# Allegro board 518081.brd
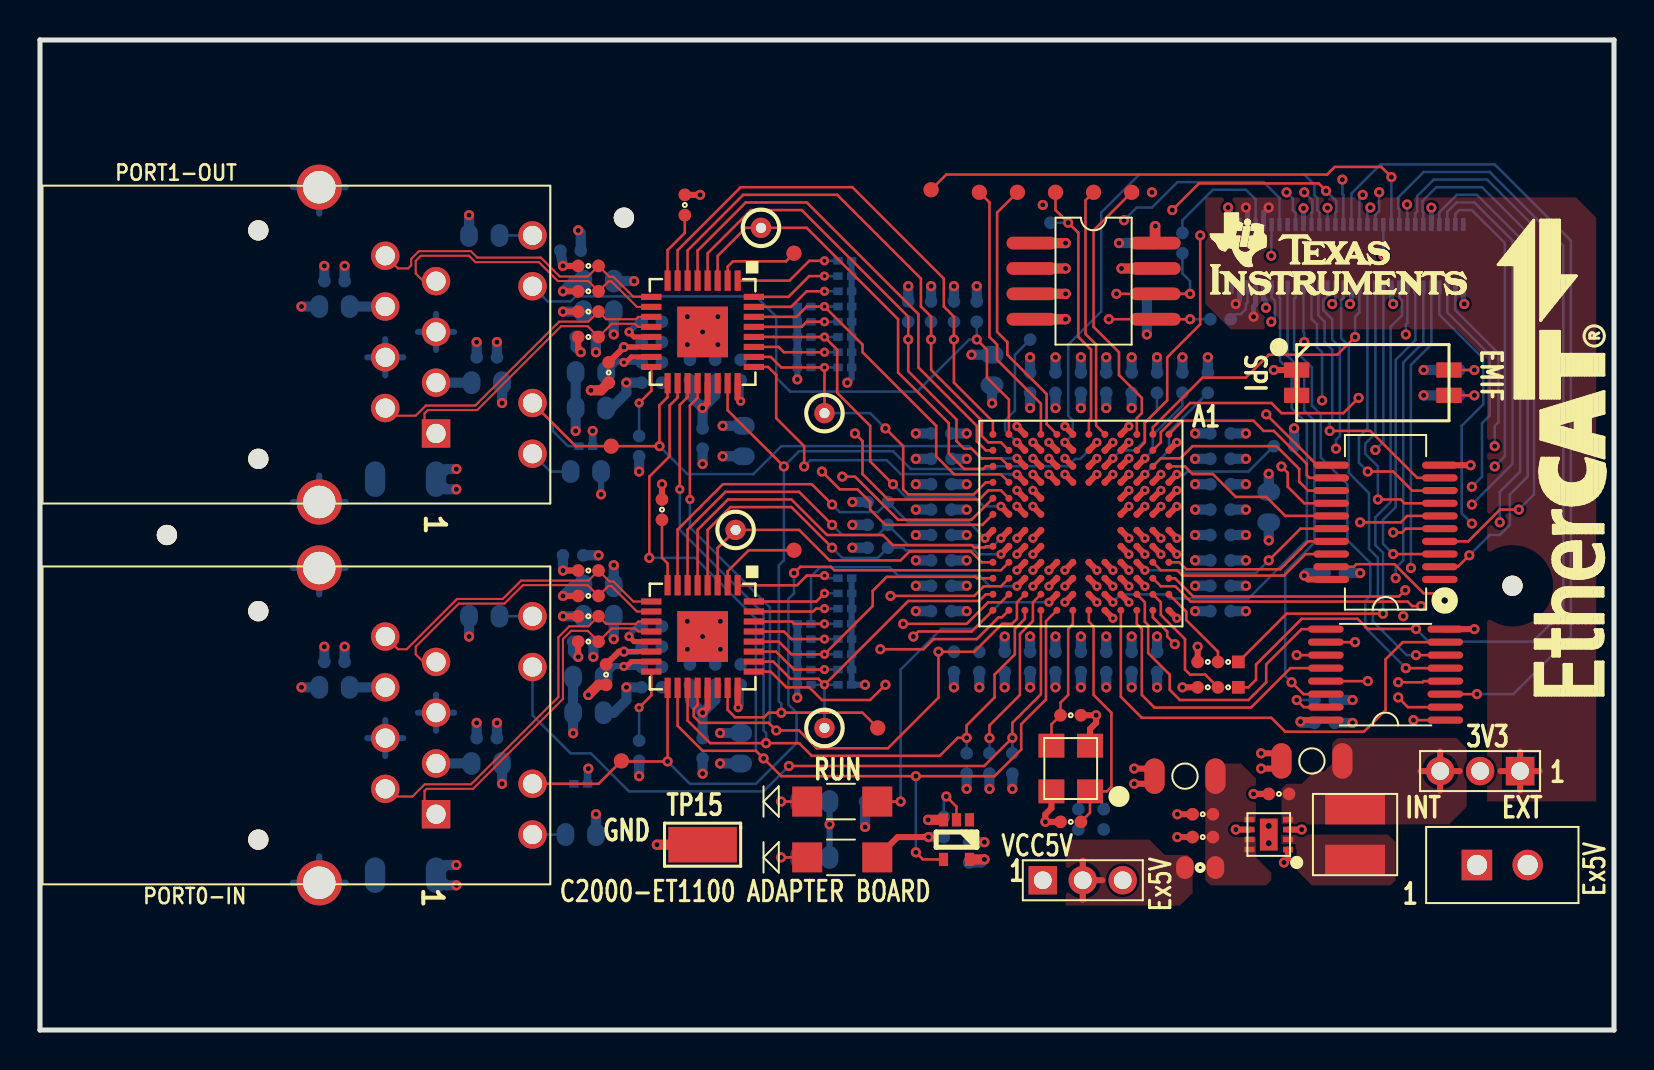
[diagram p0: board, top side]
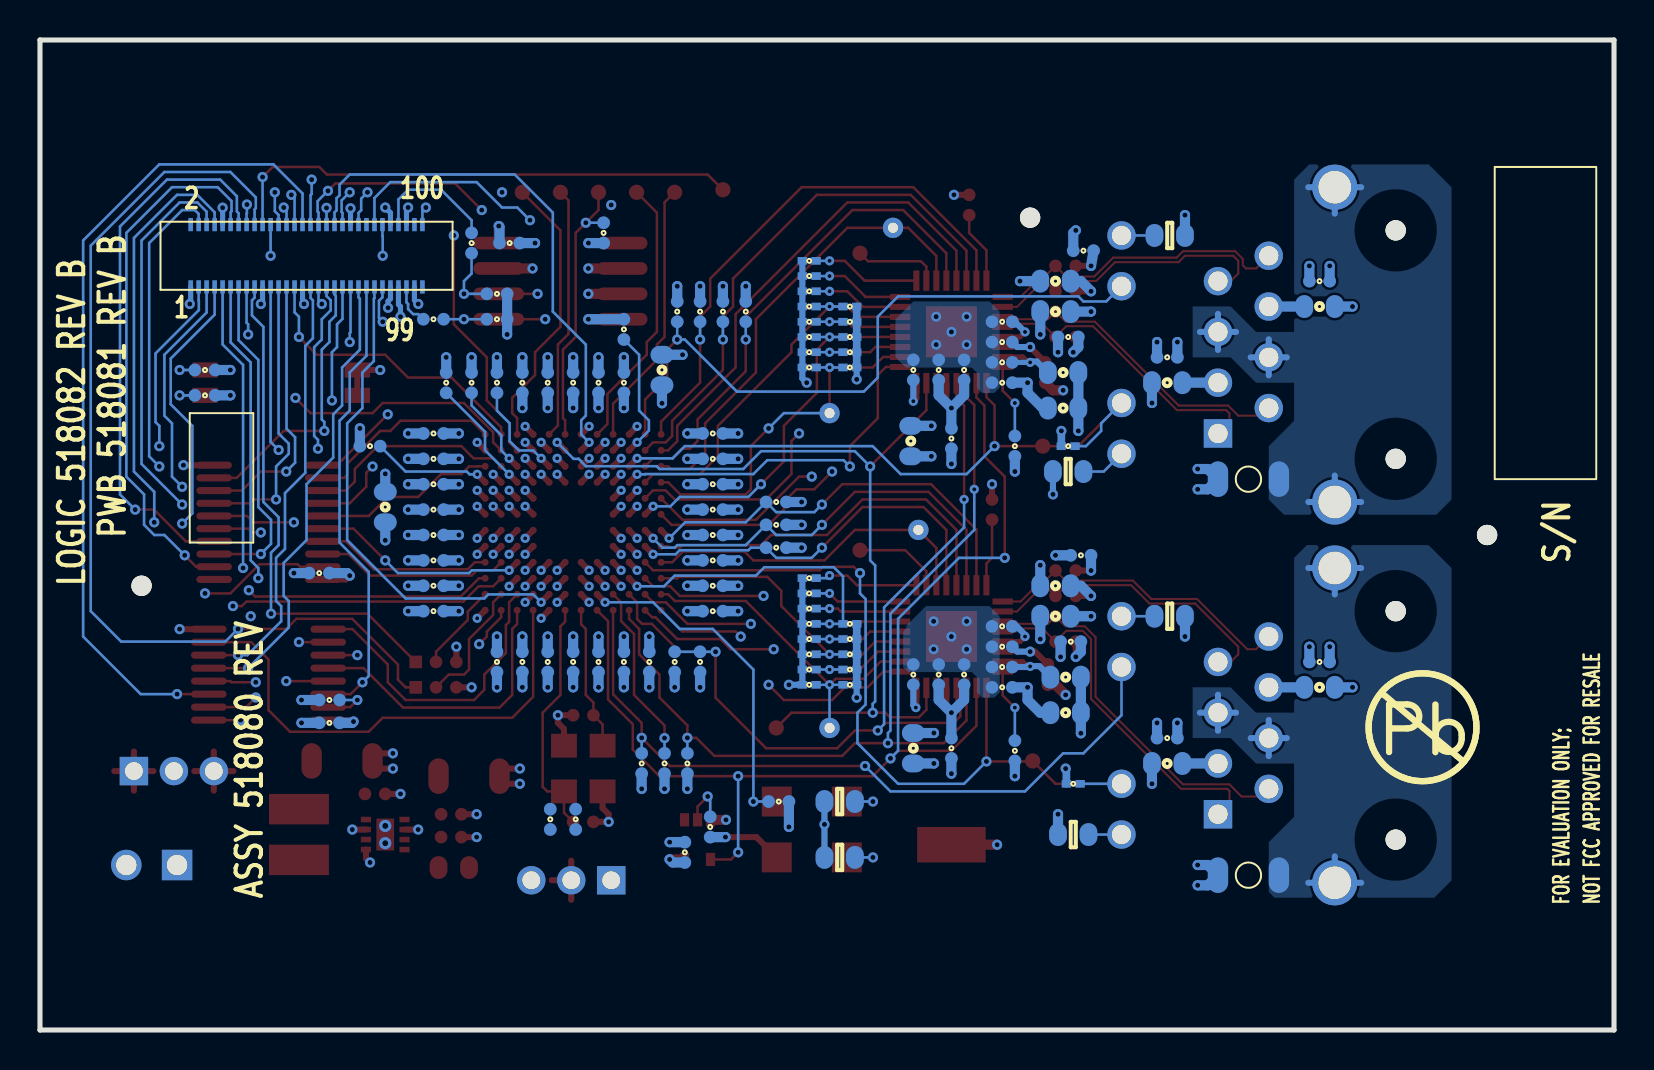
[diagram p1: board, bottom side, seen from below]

Outline 78.74 x 49.53 mm; copper layers: TOP, L2_GND, L3_ROUTE, L4_ROUTE, L5_PWR, BOTTOM. Coordinates in mm from the lower left corner of the outline.
Outline path: 0,49.53 78.74,49.53 78.74,0 0,0 0,49.53

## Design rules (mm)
net group MII0_RX1: nets MII0_RXM1 MII0_RXP1
net group MII0_TX1: nets MII0_TXM1 MII0_TXP1
net group MII1_RX1: nets MII1_RXM1 MII1_RXP1
net group MII1_TX1: nets MII1_TXM1 MII1_TXP1

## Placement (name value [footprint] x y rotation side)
C1  100pF  [C402-25]  28.45 32.89 270 top
C2  100pF  [C402-25]  28.32 17.78 270 top
C3  COMPONENTVALUE  [C402-25]  51.56 15.75 0 top
C4  X  [C1206-40X70]  63.63 13.46 180 top
C5  COMPONENTVALUE  [C402-25]  61.98 11.81 180 top
C6  X  [C1206-40X70]  57.28 12.7 180 top
C7  COMPONENTVALUE  [C402-25]  51.56 10.41 180 top
C8  COMPONENTVALUE  [C402-25]  58.17 10.79 180 top
C9  COMPONENTVALUE  [C402-25]  58.17 9.65 180 top
C10  COMPONENTVALUE  [C402-25]  46.48 8.89 90 bottom
C11  0.1uF  [C402-25]  26.54 38.99 180 bottom
C12  1uF  [C603-35X45]  27.94 37.47 0 bottom
C13  0.1uF  [C402-25]  14.73 37.47 180 bottom
C14  1uF  [C603-35X45]  14.73 36.2 180 bottom
C15  1uF  [C603-35X45]  27.94 35.94 180 bottom
C16  0.1uF  [C402-25]  30.61 35.43 0 bottom
C17  0.1uF  [C402-25]  27.3 34.67 0 bottom
C18  10nF  [C402-25]  30.61 34.42 0 bottom
C19  COMPONENTVALUE  [C402-25]  64.77 22.86 0 bottom
C20  0.1uF  [C402-25]  22.35 33.66 0 bottom
C21  0.1uF  [C402-25]  30.61 33.4 0 bottom
C22  X  [C603-35X45]  47.62 33.02 90 bottom
C23  0.1uF  [C402-25]  35.05 33.02 90 bottom
C24  10nF  [C402-25]  33.78 33.02 90 bottom
C25  1nF  [C402-25]  32.51 33.02 90 bottom
C26  10uF  [C603-35X45]  27.56 32.89 180 bottom
C27  COMPONENTVALUE  [C402-25]  54.61 32.38 90 bottom
C28  COMPONENTVALUE  [C402-25]  53.34 32.38 90 bottom
C29  COMPONENTVALUE  [C402-25]  52.07 32.38 90 bottom
C30  COMPONENTVALUE  [C402-25]  50.8 32.38 90 bottom
C31  COMPONENTVALUE  [C402-25]  49.53 32.38 90 bottom
C32  1nF  [C402-25]  30.61 32.38 0 bottom
C33  1uF  [C603-35X45]  22.35 32.38 0 bottom
C34  10uF  [C603-35X45]  27.56 31.11 180 bottom
C35  COMPONENTVALUE  [C402-25]  59.05 29.84 0 bottom
C36  COMPONENTVALUE  [C402-25]  45.09 29.84 180 bottom
C37  100pF  [C402-25]  33.15 29.59 270 bottom
C38  10uF  [C603-35X45]  35.18 29.46 270 bottom
C39  COMPONENTVALUE  [C402-25]  59.05 28.57 0 bottom
C40  COMPONENTVALUE  [C402-25]  45.09 28.57 180 bottom
C41  4700pF  [C1206-40X70]  18.29 27.56 180 bottom
C42  COMPONENTVALUE  [C402-25]  59.05 27.3 0 bottom
C43  COMPONENTVALUE  [C402-25]  45.09 27.3 180 bottom
C44  X  [C603-35X45]  61.47 26.16 90 bottom
C45  COMPONENTVALUE  [C402-25]  59.05 26.04 0 bottom
C46  COMPONENTVALUE  [C402-25]  45.09 26.04 180 bottom
C47  COMPONENTVALUE  [C402-25]  55.24 39.37 0 bottom
C48  COMPONENTVALUE  [C402-25]  59.05 24.77 0 bottom
C49  COMPONENTVALUE  [C402-25]  45.09 24.77 180 bottom
C50  0.1uF  [C402-25]  26.67 23.75 0 bottom
C51  COMPONENTVALUE  [C402-25]  59.05 23.5 0 bottom
C52  COMPONENTVALUE  [C402-25]  45.09 23.5 180 bottom
C53  COMPONENTVALUE  [C402-25]  59.05 22.23 0 bottom
C54  COMPONENTVALUE  [C402-25]  45.09 22.23 180 bottom
C55  1uF  [C603-35X45]  27.94 22.23 0 bottom
C56  COMPONENTVALUE  [C402-25]  59.05 20.95 0 bottom
C57  COMPONENTVALUE  [C402-25]  45.09 20.95 180 bottom
C58  1uF  [C603-35X45]  27.94 20.7 180 bottom
C59  0.1uF  [C402-25]  30.61 20.19 0 bottom
C60  0.1uF  [C402-25]  27.18 19.43 180 bottom
C61  10nF  [C402-25]  30.61 19.18 0 bottom
C62  COMPONENTVALUE  [C402-25]  55.88 18.41 270 bottom
C63  COMPONENTVALUE  [C402-25]  54.61 18.41 270 bottom
C64  COMPONENTVALUE  [C402-25]  53.34 18.41 270 bottom
C65  COMPONENTVALUE  [C402-25]  52.07 18.41 270 bottom
C66  COMPONENTVALUE  [C402-25]  50.8 18.41 270 bottom
C67  COMPONENTVALUE  [C402-25]  49.53 18.41 270 bottom
C68  COMPONENTVALUE  [C402-25]  48.26 18.41 270 bottom
C69  0.1uF  [C402-25]  14.73 18.41 180 bottom
C70  0.1uF  [C402-25]  30.61 18.16 0 bottom
C71  0.1uF  [C402-25]  35.05 17.78 90 bottom
C72  10nF  [C402-25]  33.78 17.78 90 bottom
C73  1nF  [C402-25]  32.51 17.78 90 bottom
C74  10uF  [C603-35X45]  27.43 17.65 180 bottom
C75  COMPONENTVALUE  [C402-25]  64.26 15.37 0 bottom
C76  1nF  [C402-25]  30.61 17.14 0 bottom
C77  1uF  [C603-35X45]  14.73 17.14 180 bottom
C78  10uF  [C603-35X45]  27.43 15.88 180 bottom
C79  0.1uF  [C402-25]  22.35 14.61 0 bottom
C80  10uF  [C603-35X45]  35.05 14.1 270 bottom
C81  100pF  [C402-25]  33.15 14.1 270 bottom
C82  1uF  [C603-35X45]  22.35 13.34 0 bottom
C83  4700pF  [C1206-40X70]  18.29 7.75 180 bottom
DS1  X  [LED1206-59X59]  40.13 11.43 0 top
DS2  X  [LED1206-59X59]  40.13 8.64 0 top
J3  X  [HDR1X3-6040-2MM]  74.04 12.95 180 top
J6  VALUE  [DF40C_60DS]  65.41 38.73 180 bottom
J9  X  [CONN2-EH]  71.88 8.26 0 top
J10  X  [HDR1X3-6040-2MM]  50.16 7.49 0 top
L1  0  [L603-35X45]  58.04 8.13 0 top
L2  X  [IND-LQH44P]  65.79 9.78 90 top
NOREF  -  [unnamed]  73.66 22.23 0 top
NOREF#2  -  [#2]  -259.21 -252.98 0 top
NOREF#3  -  [#2]  -259.21 -252.98 0 top
NOREF#4  -  [unnamed]  29.21 40.64 0 top
NOREF#5  -  [#2]  85.98 16.76 0 top
NOREF#6  -  [unnamed]  6.35 24.77 0 top
NOREF#7  -  [#2]  12.95 11.68 180 bottom
P0  -  [RJ45-PULSE_J1-SHLD]  19.81 10.79 270 top
P1  -  [RJ45-PULSE_J1-SHLD]  19.81 29.84 270 top
R1  10K  [R402-25]  32.26 41.27 270 top
R2  49.9  [R402-25]  27.43 38.23 180 top
R3  49.9  [R402-25]  27.43 36.96 180 top
R4  49.9  [R402-25]  27.43 35.94 180 top
R5  49.9  [R402-25]  27.43 34.67 180 top
R6  COMPONENTVALUE  [R402-25]  59.05 35.56 0 bottom
R7  COMPONENTVALUE  [R402-25]  57.15 39.37 270 bottom
R8  10K  [R402-25]  31.11 26.04 270 top
R9  49.9  [R402-25]  27.43 22.99 180 top
R10  49.9  [R402-25]  27.43 21.72 180 top
R11  49.9  [R402-25]  27.43 20.7 180 top
R12  49.9  [R402-25]  27.43 19.43 180 top
R13  COMPONENTVALUE  [R402-25]  45.21 10.16 270 bottom
R14  X  [R603-35X45]  22.23 39.75 180 bottom
R15  2.2K  [R201-18P5X15]  40.26 38.48 0 bottom
R16  2.2K  [R201-18P5X15]  40.26 37.72 0 bottom
R17  2.2K  [R201-18P5X15]  40.26 36.96 0 bottom
R18  COMPONENTVALUE  [R402-25]  57.15 32.38 90 bottom
R19  COMPONENTVALUE  [R402-25]  58.42 32.38 90 bottom
R20  COMPONENTVALUE  [R402-25]  55.88 32.38 90 bottom
R21  COMPONENTVALUE  [R402-25]  50.55 39.88 90 bottom
R22  2.2K  [R201-18P5X15]  40.26 36.2 0 bottom
R23  NO-POP  [R201-18P5X15]  38.23 36.2 0 bottom
R24  COMPONENTVALUE  [R402-25]  49.53 35.05 90 bottom
R25  COMPONENTVALUE  [R402-25]  46.86 35.94 90 bottom
R26  COMPONENTVALUE  [R402-25]  45.72 35.94 90 bottom
R27  COMPONENTVALUE  [R402-25]  44.58 35.94 90 bottom
R28  COMPONENTVALUE  [R402-25]  43.43 35.94 90 bottom
R29  NO-POP  [R201-18P5X15]  40.26 35.43 0 bottom
R30  2.2K  [R201-18P5X15]  38.23 35.43 0 bottom
R31  NO-POP  [R201-18P5X15]  40.26 34.67 0 bottom
R32  2.2K  [R201-18P5X15]  38.23 34.67 0 bottom
R33  COMPONENTVALUE  [R402-25]  70.48 33.02 180 bottom
R34  COMPONENTVALUE  [R402-25]  70.48 31.75 180 bottom
R35  NO-POP  [R201-18P5X15]  40.26 33.91 0 bottom
R36  2.2K  [R201-18P5X15]  38.23 33.91 0 bottom
R37  2.2K  [R201-18P5X15]  40.26 33.15 0 bottom
R38  NO-POP  [R201-18P5X15]  38.23 33.15 0 bottom
R39  COMPONENTVALUE  [R402-25]  62.23 29.21 180 bottom
R40  4.87K 1%  [R402-25]  29.97 29.21 270 bottom
R41  2.2K  [R201-18P5X15]  27.3 29.21 180 bottom
R42  COMPONENTVALUE  [R402-25]  55.88 35.56 180 bottom
R43  330  [R603-35X45]  27.3 27.94 0 bottom
R44  COMPONENTVALUE  [R402-25]  55.88 36.83 180 bottom
R45  COMPONENTVALUE  [R402-25]  41.91 26.42 180 bottom
R46  COMPONENTVALUE  [R402-25]  41.91 25.27 180 bottom
R47  COMPONENTVALUE  [R402-25]  41.91 24.13 180 bottom
R48  2.2K  [R201-18P5X15]  40.26 22.61 0 bottom
R49  2.2K  [R201-18P5X15]  40.26 21.84 0 bottom
R50  2.2K  [R201-18P5X15]  40.26 21.08 0 bottom
R51  X  [R603-35X45]  22.23 20.7 180 bottom
R52  2.2K  [R201-18P5X15]  40.26 20.32 0 bottom
R53  NO-POP  [R201-18P5X15]  38.23 20.32 0 bottom
R54  2.2K  [R201-18P5X15]  40.26 19.56 0 bottom
R55  NO-POP  [R201-18P5X15]  38.23 19.56 0 bottom
R56  NO-POP  [R201-18P5X15]  40.26 18.8 0 bottom
R57  2.2K  [R201-18P5X15]  38.23 18.8 0 bottom
R58  COMPONENTVALUE  [R402-25]  64.26 16.51 180 bottom
R59  COMPONENTVALUE  [R402-25]  46.99 18.41 270 bottom
R60  COMPONENTVALUE  [R402-25]  45.72 18.41 270 bottom
R61  NO-POP  [R201-18P5X15]  40.26 18.03 0 bottom
R62  2.2K  [R201-18P5X15]  38.23 18.03 0 bottom
R63  2.2K  [R201-18P5X15]  40.26 17.27 0 bottom
R64  NO-POP  [R201-18P5X15]  38.23 17.27 0 bottom
R65  4.87K 1%  [R402-25]  29.97 13.97 270 bottom
R66  COMPONENTVALUE  [R402-25]  48.64 13.34 270 bottom
R67  COMPONENTVALUE  [R402-25]  47.5 13.34 270 bottom
R68  COMPONENTVALUE  [R402-25]  46.35 13.34 270 bottom
R69  2.2K  [R201-18P5X15]  27.05 12.32 180 bottom
R70  COMPONENTVALUE  [R402-25]  53.21 10.54 90 bottom
R71  COMPONENTVALUE  [R402-25]  51.94 10.54 90 bottom
R72  X  [R603-35X45]  38.73 11.43 180 bottom
R73  COMPONENTVALUE  [R402-25]  41.78 11.43 180 bottom
R74  330  [R603-35X45]  27.05 9.78 0 bottom
R75  X  [R603-35X45]  38.73 8.64 180 bottom
RJ1  COMPONENTVALUE  [JMP402-25]  59.44 18.41 180 top
RJ2  COMPONENTVALUE  [JMP402-25]  59.44 17.14 180 top
SW1  X  [SW2-30X50-TDA]  66.67 32.38 270 top
TP1  -  [TP1-4020]  36.07 40.13 0 top
TP2  COMPONENTVALUE  [TP30]  46.99 41.91 90 top
TP3  COMPONENTVALUE  [TP30]  48.9 41.91 90 top
TP4  COMPONENTVALUE  [TP30]  50.8 41.91 90 top
TP5  COMPONENTVALUE  [TP30]  52.7 41.91 90 top
TP6  COMPONENTVALUE  [TP30]  54.61 41.91 90 top
TP7  COMPONENTVALUE  [TP30]  37.72 38.86 0 top
TP8  -  [TP1-4020]  39.24 30.86 0 top
TP9  TestPoint1  [TP30]  28.57 29.21 270 top
TP10  -  [TP1-4020]  34.8 25.02 0 top
TP11  COMPONENTVALUE  [TP30]  37.72 24 0 top
TP12  -  [TP1-4020]  39.24 15.11 0 top
TP13  COMPONENTVALUE  [TP30]  41.91 15.11 0 top
TP14  TestPoint1  [TP30]  29.08 13.46 270 top
TP15  -  [TP1-70X135]  33.15 9.27 270 top
TP16  COMPONENTVALUE  [TP30]  44.58 42.04 0 top
U1  VALUE  [DCK-5]  45.85 9.53 180 top
U2  X  [DBQ20-14X70]  67.31 25.4 90 top
U3  TLK105  [QFN32_202SQ]  33.15 34.92 180 top
U4  X  [SO8-25X75-295]  52.7 37.47 270 top
U5  -  [BGA128-8MM]  52.07 25.4 270 top
U6  TLK105  [QFN32_202SQ]  33.15 19.68 180 top
U7  X  [TSSOP16-14X70]  67.31 17.78 90 top
U8  X  [DSG8-11X20]  61.47 9.78 90 top
Y1  -  [XTAL4-47X51-ECX32]  51.56 13.08 90 top

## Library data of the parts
C1 C2 C8 C10 C11 C16-C19 C21 C23-C25 C27-C32 C35-C37 C39 C40 C42 C43 C45 C46 C48-C54 C56 C57 C59-C68 C70-C73 C75 C76 C81 = CAP NP: Tolerance: TOLERANCE; User Part Number: USERPART#
C3 C7 = CAP NP_3: Tolerance: TOLERANCE; User Part Number: USERPART#
C4 C6 = CAP P_0
C5 C9 = CAP NP_1: Tolerance: TOLERANCE; User Part Number: USERPART#
C12 C14 C15 C26 C33 C34 C38 C55 C58 C74 C77 C78 C80 C82 = CAP NP: Tolerance: X; User Part Number: X
C13 C20 C69 C79 = CAP NP_0: Tolerance: TOLERANCE; User Part Number: USERPART#
C22 C44 = CAP NP
C41 C83 = CAP NP_0: Tolerance: X; User Part Number: X
C47 = CAP .1 uF 10% 0603: Tolerance: TOLERANCE; User Part Number: USERPART#
DS1 DS2 = LED_0
J3 J10 = HEADER 3
J6 = HEADER 30x2/SM: Tolerance: TOL; User Part Number: PART#
J9 = HEADER 2
L1 = FERRITE CHIP_0: Tolerance: X; User Part Number: X
L2 = INDUCTOR_0
P0 P1 = J1011F01PNL
R1-R12 R21 R39 R58 R70 R71 = R: Tolerance: TOLERANCE; User Part Number: USERPART#
R13 R18-R20 R24-R28 R33 R34 R40 R42 R44-R47 R59 R60 R65-R68 R73 = RESISTOR_0: Tolerance: TOLERANCE; User Part Number: USERPART#
R14 R51 R72 R75 = RESISTOR_0
R15-R17 R22 R23 R29-R32 R35-R38 R41 R48-R50 R52-R57 R61-R64 R69 = RESISTOR_0: User Part Number: USERPART#; Tolerance: TOLERANCE
R43 R74 = RESISTOR_0: User Part Number: X; Tolerance: X
RJ1 RJ2 = RJUMP3: Tolerance: TOLERANCE; User Part Number: USERPART#
SW1 = SW DIP-2
TP1 TP8 TP10 TP12 = TEST POINT_1
TP2-TP7 TP9 TP11 TP13 TP14 TP16 = TestPoint1: Tolerance: TOLERANCE; User Part Number: USERPART#
TP15 = SMT-TP
U1 = SN74LVC1GU04_0: Tolerance: TOL; User Part Number: PART#
U2 = 74PCT245_0
U3 U6 = TLK105: Tolerance: TOL; User Part Number: PART#
U4 = 24WC256
U5 = ET1100
U7 = SN74CBT3257PW
U8 = TPS62000
Y1 = CRYSTAL 4-PIN_0

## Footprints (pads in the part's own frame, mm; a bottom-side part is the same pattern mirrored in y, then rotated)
BGA128-8MM
  round 0.351 smd: A1(-4.401,4.401) A2(-3.6,4.401) A3(-2.8,4.401) A4(-2,4.401) A5(-1.2,4.401) A6(-0.4,4.401) A7(0.4,4.401) A8(1.2,4.401) A9(2,4.401) A10(2.8,4.401) A11(3.6,4.401) A12(4.401,4.401) B1(-4.401,3.6) B2(-3.6,3.6) B3(-2.8,3.6) B4(-2,3.6) B5(-1.2,3.6) B6(-0.4,3.6) B7(0.4,3.6) B8(1.2,3.6) B9(2,3.6) B10(2.8,3.6) B11(3.6,3.6) B12(4.401,3.6) C1(-4.401,2.8) C2(-3.6,2.8) C3(-2.8,2.8) C4(-2,2.8) C5(-1.2,2.8) C6(-0.4,2.8) C7(0.4,2.8) C8(1.2,2.8) C9(2,2.8) C10(2.8,2.8) C11(3.6,2.8) C12(4.401,2.8) D1(-4.401,2) D2(-3.6,2) D3(-2.8,2) D4(-2,2) D5(-1.2,2) D6(-0.4,2) D7(0.4,2) D8(1.2,2) D9(2,2) D10(2.8,2) D11(3.6,2) D12(4.401,2) E1(-4.401,1.2) E2(-3.6,1.2) E3(-2.8,1.2) E4(-2,1.2) E9(2,1.2) E10(2.8,1.2) E11(3.6,1.2) E12(4.401,1.2) F1(-4.401,0.4) F2(-3.6,0.4) F3(-2.8,0.4) F4(-2,0.4) F9(2,0.4) F10(2.8,0.4) F11(3.6,0.4) F12(4.401,0.4) G1(-4.401,-0.4) G2(-3.6,-0.4) G3(-2.8,-0.4) G4(-2,-0.4) G9(2,-0.4) G10(2.8,-0.4) G11(3.6,-0.4) G12(4.401,-0.4) H1(-4.401,-1.2) H2(-3.6,-1.2) H3(-2.8,-1.2) H4(-2,-1.2) H9(2,-1.2) H10(2.8,-1.2) H11(3.6,-1.2) H12(4.401,-1.2) J1(-4.401,-2) J2(-3.6,-2) J3(-2.8,-2) J4(-2,-2) J5(-1.2,-2) J6(-0.4,-2) J7(0.4,-2) J8(1.2,-2) J9(2,-2) J10(2.8,-2) J11(3.6,-2) J12(4.401,-2) K1(-4.401,-2.8) K2(-3.6,-2.8) K3(-2.8,-2.8) K4(-2,-2.8) K5(-1.2,-2.8) K6(-0.4,-2.8) K7(0.4,-2.8) K8(1.2,-2.8) K9(2,-2.8) K10(2.8,-2.8) K11(3.6,-2.8) K12(4.401,-2.8) L1(-4.401,-3.6) L2(-3.6,-3.6) L3(-2.8,-3.6) L4(-2,-3.6) L5(-1.2,-3.6) L6(-0.4,-3.6) L7(0.4,-3.6) L8(1.2,-3.6) L9(2,-3.6) L10(2.8,-3.6) L11(3.6,-3.6) L12(4.401,-3.6) M1(-4.401,-4.401) M2(-3.6,-4.401) M3(-2.8,-4.401) M4(-2,-4.401) M5(-1.2,-4.401) M6(-0.4,-4.401) M7(0.4,-4.401) M8(1.2,-4.401) M9(2,-4.401) M10(2.8,-4.401) M11(3.6,-4.401) M12(4.401,-4.401)
C402-25
  round 0.635 smd: 1(-0.508,0) 2(0.508,0)
C603-35X45
  oval 0.889x1.143 smd: 1(-0.762,0) 2(0.762,0)
C1206-40X70
  oval 1.016x1.778 smd: 1(-1.524,0) 2(1.524,0)
CONN2-EH
  rect 1.524x1.524 hole 1.016: 1(0,0)
  round 1.524 hole 1.016: 2(2.54,0)
DBQ20-14X70
  oval 0.356x1.778 smd: 1(-2.857,-2.718) 2(-2.223,-2.718) 3(-1.587,-2.718) 4(-0.953,-2.718) 5(-0.318,-2.718) 6(0.318,-2.718) 7(0.953,-2.718) 8(1.587,-2.718) 9(2.223,-2.718) 10(2.857,-2.718) 11(2.857,2.718) 12(2.223,2.718) 13(1.587,2.718) 14(0.953,2.718) 15(0.318,2.718) 16(-0.318,2.718) 17(-0.953,2.718) 18(-1.587,2.718) 19(-2.223,2.718) 20(-2.857,2.718)
DCK-5
  rect 0.46x0.66 smd: 1(-0.65,-0.991) 2(0,-0.991) 3(0.65,-0.991) 4(0.65,0.991) 5(-0.65,0.991)
DF40C_60DS
  rect 0.229x0.66 smd: 1(-5.796,-1.56) 2(-5.796,1.56) 3(-5.397,-1.56) 4(-5.397,1.56) 5(-4.999,-1.56) 6(-4.999,1.56) 7(-4.597,-1.56) 8(-4.597,1.56) 9(-4.199,-1.56) 10(-4.199,1.56) 11(-3.797,-1.56) 12(-3.797,1.56) 13(-3.399,-1.56) 14(-3.399,1.56) 15(-3,-1.56) 16(-3,1.56) 17(-2.598,-1.56) 18(-2.598,1.56) 19(-2.2,-1.56) 20(-2.2,1.56) 21(-1.798,-1.56) 22(-1.798,1.56) 23(-1.4,-1.56) 24(-1.4,1.56) 25(-1.001,-1.56) 26(-1.001,1.56) 27(-0.599,-1.56) 28(-0.599,1.56) 29(-0.201,-1.56) 30(-0.201,1.56) 31(0.201,-1.56) 32(0.201,1.56) 33(0.599,-1.56) 34(0.599,1.56) 35(0.998,-1.56) 36(0.998,1.56) 37(1.4,-1.56) 38(1.4,1.56) 39(1.798,-1.56) 40(1.798,1.56) 41(2.2,-1.56) 42(2.2,1.56) 43(2.598,-1.56) 44(2.598,1.56) 45(2.997,-1.56) 46(2.997,1.56) 47(3.399,-1.56) 48(3.399,1.56) 49(3.797,-1.56) 50(3.797,1.56) 51(4.199,-1.56) 52(4.199,1.56) 53(4.597,-1.56) 54(4.597,1.56) 55(4.999,-1.56) 56(4.999,1.56) 57(5.397,-1.56) 58(5.397,1.56) 59(5.796,-1.56) 60(5.796,1.56)
DSG8-11X20
  rect 0.279x0.508 smd: 1(-0.75,-0.965) 2(-0.25,-0.965) 3(0.25,-0.965) 4(0.75,-0.965) 5(0.75,0.965) 6(0.25,0.965) 7(-0.25,0.965) 8(-0.75,0.965)
  rect 1.6x0.889 smd: 9(0,0)
HDR1X3-6040-2MM
  rect 1.422x1.422 hole 0.889: 1(0,0)
  round 1.422 hole 0.889: 2(1.999,0) 3(3.998,0)
IND-LQH44P
  rect 1.524x2.997 smd: 1(-1.27,0) 2(1.27,0)
JMP402-25
  rect 0.635x0.635 smd: 1(-0.508,0)
  round 0.635 smd: 2(0.508,0) 3(1.524,0)
L603-35X45
  oval 0.889x1.143 smd: 1(-0.762,0) 2(0.762,0)
LED1206-59X59
  rect 1.499x1.499 smd: 1(-1.753,0) 2(1.753,0)
QFN32_202SQ
  rect 0.305x1.016 smd: 1(-1.753,-2.565) 2(-1.252,-2.565) 3(-0.752,-2.565) 4(-0.251,-2.565) 5(0.251,-2.565) 6(0.752,-2.565) 7(1.252,-2.565) 8(1.753,-2.565) 17(1.753,2.565) 18(1.252,2.565) 19(0.752,2.565) 20(0.251,2.565) 21(-0.251,2.565) 22(-0.752,2.565) 23(-1.252,2.565) 24(-1.753,2.565)
  rect 1.016x0.305 smd: 9(2.565,-1.753) 10(2.565,-1.252) 11(2.565,-0.752) 12(2.565,-0.251) 13(2.565,0.251) 14(2.565,0.752) 15(2.565,1.252) 16(2.565,1.753) 25(-2.565,1.753) 26(-2.565,1.252) 27(-2.565,0.752) 28(-2.565,0.251) 29(-2.565,-0.251) 30(-2.565,-0.752) 31(-2.565,-1.252) 32(-2.565,-1.753)
  rect 2.54x2.54 smd: 33(0,0)
R201-18P5X15
  rect 0.47x0.381 smd: 1(-0.343,0) 2(0.343,0)
R402-25
  round 0.635 smd: 1(-0.508,0) 2(0.508,0)
R603-35X45
  oval 0.889x1.143 smd: 1(-0.762,0) 2(0.762,0)
RJ45-PULSE_J1-SHLD
  round 1.016 hole 3.251 unplated: (-10.16,-8.89) (1.27,-8.89)
  rect 1.422x1.422 hole 0.965: 1(0,0)
  round 1.422 hole 0.965: 2(-1.27,-2.54) 3(-2.54,0) 4(-3.81,-2.54) 5(-5.08,0) 6(-6.35,-2.54) 7(-7.62,0) 8(-8.89,-2.54) 9(1.016,4.826) 10(-1.524,4.826) 11(-7.366,4.826) 12(-9.906,4.826)
  round 2.261 hole 1.626: 13(-12.319,-5.842) 14(3.429,-5.842)
SO8-25X75-295
  oval 0.635x2.54 smd: 1(-1.905,-3.086) 2(-0.635,-3.086) 3(0.635,-3.086) 4(1.905,-3.086) 5(1.905,3.086) 6(0.635,3.086) 7(-0.635,3.086) 8(-1.905,3.086)
SW2-30X50-TDA
  rect 0.762x1.27 smd: 1(-0.635,-3.81) 2(0.635,-3.81) 3(0.635,3.81) 4(-0.635,3.81)
TP1-70X135
  rect 1.778x3.429 smd: 1(0,0)
TP1-4020
  round 1.016 hole 0.508: 1(0,0)
TP30
  round 0.762 smd: 1(0,0)
TSSOP16-14X70
  oval 0.356x1.778 smd: 1(-2.276,-2.987) 2(-1.626,-2.987) 3(-0.975,-2.987) 4(-0.325,-2.987) 5(0.325,-2.987) 6(0.975,-2.987) 7(1.626,-2.987) 8(2.276,-2.987) 9(2.276,2.987) 10(1.626,2.987) 11(0.975,2.987) 12(0.325,2.987) 13(-0.325,2.987) 14(-0.975,2.987) 15(-1.626,2.987) 16(-2.276,2.987)
unnamed
  round 1.016 hole 2.489 unplated: (0,0)
XTAL4-47X51-ECX32
  rect 1.194x1.295 smd: 1(-1.143,-0.965) 2(1.143,-0.965) 3(1.143,0.965) 4(-1.143,0.965)

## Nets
GND: C1.2 C2.2 C3.2 C4.2 C5.2 C6.2 C7.2 C8.2 C9.2 C10.2 C11.1 C12.2 C13.2 C14.2 C15.1 C16.2 C17.2 C18.2 C19.2 C20.2 C21.2 C22.2 C23.2 C24.2 C25.2 C26.2 C27.2 C28.2 C29.2 C30.2 C31.2 C32.2 C33.2 C34.2 C35.2 C36.2 C37.2 C38.2 C39.2 C40.2 C41.1 C42.2 C43.2 C44.2 C45.2 C46.2 C47.1 C48.2 C49.2 C50.2 C51.2 C52.2 C53.2 C54.2 C55.2 C56.2 C57.2 C58.1 C59.2 C60.1 C61.2 C62.2 C63.2 C64.2 C65.2 C66.2 C67.2 C68.2 C69.2 C70.2 C71.2 C72.2 C73.2 C74.2 C75.2 C76.2 C77.2 C78.2 C79.2 C80.2 C81.2 C82.2 C83.1 J6.1 J6.10 J6.19 J6.29 J6.42 J6.51 J9.2 R15.2 R16.2 R17.2 R18.2 R19.2 R20.2 R21.1 R22.2 R24.2 R26.2 R27.2 R28.2 R29.2 R31.2 R35.2 R37.2 R39.1 R40.2 R45.2 R46.2 R47.2 R48.2 R49.2 R50.2 R52.2 R54.2 R56.2 R58.1 R59.2 R61.2 R63.2 R65.2 R67.2 R72.1 R73.2 R75.1 RJ1.3 RJ2.3 SW1.1(A1) SW1.2(A2) TP15.1 U1.3(GND) U2.10(GND) U3.33(GND) U4.1(A0) U4.2(A1) U4.3(NC) U4.4(VSS) U4.7(WP) U5.C8(NC5) U5.D4(GNDIO1) U5.D5(GNDIO0) U5.D6(GNDCORE0) U5.D7(GNDCORE3) U5.D8(NC8) U5.D9(GNDIO7) U5.E4(NC1) U5.E10(NC4) U5.F4(NC7) U5.F9(GNDIO6) U5.G3(NC2) U5.G4(NC3) U5.G9(GNDPLL) U5.H3(TESTMODE) U5.H4(TCFG[1]GNDIO9) U5.H10(NC6) U5.J4(GNDIO2) U5.J5(GNDIO3) U5.J6(GNDCORE1) U5.J7(GNDCORE2) U5.J8(GNDIO4) U5.J9(GNDIO5) U5.K9(TCFG[2]/GNDIO10) U6.33(GND) U7.8(GND) U8.1(PGND) U8.3(AGND) U8.6(MODE) U8.9(PAD) Y1.2(C1) Y1.4(C2)
VCC_2V5: C42.1 C43.1 C44.1 C45.1 C46.1 C48.1 C49.1 C51.1 C52.1 C65.1 C66.1 U5.C6(VCCCORE0) U5.C7(VCCCORE3) U5.G10(VCCPLL) U5.K6(VCCCORE1) U5.K7(VCCCORE2)
VCC_3V3: J3.1 J6.52 J6.53 J6.56 J6.57
VCC_5V: J10.1
CLK_MODE[0]: R67.1 U5.J11(PERR{0}/TRANS{0}/CLK-MODE[0])
CLK_MODE[1]: R24.1 U5.K2(PERR{1}/TRANS{1}/CLK-MODE[1])
EEPROM_SIZE: DS1.2(ANODE) R73.1 U5.H11(RUN/EEPROM-SIZE)
EM2A9: J6.12 U2.2(A1)
EM2A10: J6.13 U2.3(A2)
EM2A11: J6.14 U2.4(A3)
EM2D1: J6.22 U2.5(A4)
EM2D2: J6.23 U2.7(A6)
EM2D3: J6.24 U2.6(A5)
EM2D4: J6.25 U2.8(A7)
EM2D11: J6.37 U2.9(A8)
ET_ADDR1: J6.3 U5.B5(PDI[21]/LINK_MII{3})
ET_ADDR2: J6.4 U5.A5(PDI[20]/RX_D{3}[3])
ET_ADDR3: J6.5 U5.B6(PDI[19]/RX_D{3}[2])
ET_ADDR4: J6.6 U5.A6(PDI[18]/RX_D{3}[0])
ET_ADDR5: J6.7 U5.B7(PDI[17]/RX_CLK{3})
ET_ADDR6: J6.8 U5.A7(PDI[16]/RX_ERR{3})
ET_ADDR7: J6.9 U5.B8(PDI[15])
ET_ADDR8: J6.11 U5.A8(PDI[14])
ET_ADDR9: U2.18(B1) U5.B9(PDI[13])
ET_ADDR10: U2.17(B2) U5.A9(PDI[12])
ET_ADDR11: U2.16(B3) U5.C9(PDI[11])
ET_ADDR12: J6.15 U5.A10(PDI[10])
ET_ADDR13: J6.16 U5.B10(PDI[09])
ET_ADDR14: RJ1.2 U5.A11(PDI[08])
ET_ADDR15: RJ2.2 U5.B11(PDI[07]/CPU_CLK_OUT)
ET_BUSY: J6.50 U7.11(3B1)
ET_BUSY/SPI_DO: U5.C11(PDI[03]) U7.9(3A)
ET_CS: J6.43 U7.5(2B1)
ET_CS/SPI_CLK: U5.D12(PDI[00]) U7.7(2A)
ET_DATA0: J6.21 U5.B4(PDI[23]/TX_D{3}[2])
ET_DATA1: U2.15(B4) U5.A3(PDI[24]/TX_D{3}[1]/EBUS{3}-TX-)
ET_DATA2: U2.13(B6) U5.B3(PDI[25]/TX_D{3}[0])
ET_DATA3: U2.14(B5) U5.A2(PDI[26]/TX_ENA{3}/EBUS{3}-TX+)
ET_DATA4: U2.12(B7) U5.A1(PDI[27]/RX_DV{3}/EBUS{3}-RX-)
ET_DATA5: J6.26 U5.B2(PDI[28]/PERR{3}/TRANS{3})
ET_DATA6: J6.27 U5.B1(PDI[29]/RX_D{3}[1]/EBUS{3}-RX+)
ET_DATA7: J6.28 U5.C2(PDI[30]/LINKACT{3}/P_CONF[3])
ET_DATA8: J6.34 U5.D1(PDI[32]/TX_D{2}[3])
ET_DATA9: J6.35 U5.D2(PDI[33]/TX_D{2}[2])
ET_DATA10: J6.36 U5.E2(PDI[34]/TX_D{2}[0]/CTL/STAT-MOV)
ET_DATA11: U2.11(B8) U5.G1(PDI[35]/RX_ERR{2})
ET_DATA12: J6.38 U5.G2(PDI[36]/RX_CLK{2})
ET_DATA13: J6.39 U5.H2(PDI[37]/RX_D{2}[0])
ET_DATA14: J6.40 U5.J2(PDI[38]/RX_D{2}[2])
ET_DATA15: J6.41 U5.K1(PDI[39]/RX_D{2}[3])
ET_EE_LOADED: J6.20 TP16.1 U5.A12(PDI[06])
ET_IRQ/SPI_IRQ: J6.49 U5.B12(PDI[04])
ET_RD: J6.44 U7.2(1B1)
ET_RD/SPI_SEL: U5.D11(PDI[01]) U7.4(1A)
ET_RESETN: J6.60 R13.1 U1.2(I)
ET_SCL: R7.2 R44.1 U4.6(SCL) U5.G11(EEPROM CLK)
ET_SDA: R6.1 R42.1 U4.5(SDA) U5.F11(EEPROM DATA)
ET_SPI_CLK: J6.31 U7.6(2B2)
ET_SPI_DI: J6.32 U7.13(4B2)
ET_SPI_DO: J6.33 U7.10(3B2)
ET_SPI_SEL: J6.30 U7.3(1B2)
ET_SYNC0: J6.47 U5.E11(SYNC[0]/LATCH[0])
ET_SYNC1: J6.48 U5.E12(SYNC[1]/LATCH[1])
ET_WR: J6.45 U7.14(4B1)
ET_WR/SPI_DI: U5.C12(PDI[02]) U7.12(4A)
EVM_3V3: C1.1 C2.1 C10.1 C11.2 C12.1 C13.1 C14.1 C15.2 C17.1 C18.1 C19.1 C20.1 C22.1 C24.1 C25.1 C27.1 C28.1 C29.1 C30.1 C31.1 C32.1 C33.1 C34.1 C35.1 C36.1 C37.1 C38.1 C39.1 C40.1 C47.2 C50.1 C53.1 C54.1 C55.1 C56.1 C57.1 C58.2 C60.2 C61.1 C62.1 C63.1 C64.1 C67.1 C68.1 C69.1 C72.1 C73.1 C75.1 C76.1 C77.1 C78.1 C79.1 C80.1 C81.1 C82.1 DS2.2(ANODE) J3.2 P0.3(TDCT) P0.6(RDCT) P1.3(TDCT) P1.6(RDCT) R1.1 R2.2 R3.2 R4.2 R5.2 R8.1 R9.2 R10.2 R11.2 R12.2 R13.2 R14.2 R23.1 R25.2 R30.1 R32.1 R33.2 R34.2 R36.1 R38.1 R41.1 R42.2 R43.2 R44.2 R51.2 R53.1 R55.1 R57.1 R60.2 R62.1 R64.1 R66.2 R68.2 R69.1 R74.2 U1.5(VCC) U2.20(VCC) U3.14(AVDD33) U3.21(VDD33_IO) U4.8(VCC) U5.C5(VCCIO0) U5.D3(VCCIO1) U5.D10(VCCIO7) U5.E9(VCCIO8) U5.F3(TCFG[0]/VCCIO10) U5.F10(VCCIO6) U5.H9(TCFG[3]/VCCIO11) U5.J3(VCCIO2) U5.J10(VCCIO5) U5.K5(VCCIO3) U5.K8(VCCIO4) U6.14(AVDD33) U6.21(VDD33_IO) U7.16(VCC)
GPIO93: J6.17 RJ1.1
GPIO94: J6.18 RJ2.1
MII0_RXM1: P0.8(RD-) R9.1 U6.9(RD-)
MII0_RXP1: P0.7(RD+) R10.1 U6.10(RD+)
MII0_TXM1: P0.2(TD-) R11.1 U6.11(TD-)
MII0_TXP1: P0.1(TD+) R12.1 U6.12(TD+)
MII1_RXM1: P1.8(RD-) R2.1 U3.9(RD-)
MII1_RXP1: P1.7(RD+) R3.1 U3.10(RD+)
MII1_TXM1: P1.2(TD-) R4.1 U3.11(TD-)
MII1_TXP1: P1.1(TD+) R5.1 U3.12(TD+)
P_CONF[2]: R20.1 U5.E3(LINKACT{2}/P-CONF[2])
PFBOUT0: C59.1 C70.1 C71.1 C74.1 U6.13(PFBIN1) U6.15(PFBOUT) U6.24(PFBIN2)
PFBOUT1: C16.1 C21.1 C23.1 C26.1 U3.13(PFBIN1) U3.15(PFBOUT) U3.24(PFBIN2)
PHYAD_OFF: R18.1 U5.C3(PERR{2}/TRANS{2}/PHYADD-OFF)
PR2_MDIO_DATA: R68.1 U3.19(MDIO) U5.K12(MI_DATA) U6.19(MDIO)
PR2_MDIO_MDCLK: R59.1 R60.1 U3.20(MDC) U5.K11(MI_CLK/LINKPOL) U6.20(MDC)
PR2_MII0_LINKACT: P0.11(C_LEFT) R66.1 U5.J12(LINKACT{0}/P-CONFIG[0])
PR2_MII0_RXCLK: U5.L10(RX_CLK{0}) U6.25(RX_CLK)
PR2_MII0_RXD0: R52.1 R53.2 U5.K10(RX_D{0}[0]) U6.30(RXD_0/PHYAD1)
PR2_MII0_RXD1: R50.1 U5.M12(RX_D{0}[1]/EBUS{0}-RX+) U6.31(RXD_1/PHYAD2)
PR2_MII0_RXD2: R49.1 U5.L11(RX_D{0}[2]) U6.32(RXD_2/PHYAD3)
PR2_MII0_RXD3: R48.1 U5.L12(RX_D{0}[3]) U6.1(RXD_3/PHYAD4)
PR2_MII0_RXDV: R63.1 R64.2 TP12.1 U5.M11(RX_DV{0}/EBUS{0}-RX-) U6.26(RX_DV/MII_MODE)
PR2_MII0_RXER: R56.1 R57.2 U5.M10(RX_ERR{0}) U6.28(RX_ER/AMDIX_EN)
PR2_MII0_RXLINK: P0.10(C_RIGHT) R69.2 TP14.1 U5.L9(LINK_MII{0}) U6.17(LED_LINK/AN_0)
PR2_MII0_TXD0: R47.1 U5.L8(TX_D{0}[0]/C25_ENA) U6.4(TXD0)
PR2_MII0_TXD1: U5.M8(TX_D{0}[1]/EBUS{0}-TX-) U6.5(TXD1)
PR2_MII0_TXD2: R46.1 U5.L7(TX_D{0}[2]\C25_SHI[0]) U6.6(TXD2)
PR2_MII0_TXD3: R45.1 U5.M7(TX_D{0}[3]\C25_SHI[1]) U6.7(TXD3)
PR2_MII0_TXEN: TP10.1 U5.M9(TX_ENA{0}/EBUS{0}-TX+) U6.3(TX_EN)
PR2_MII1_LINKACT: P1.11(C_LEFT) R25.1 U5.L1(LINKACT{1}/P-CONF[1])
PR2_MII1_RXCLK: U3.25(RX_CLK) U5.K4(RX_CLK{1})
PR2_MII1_RXD0: R22.1 R23.2 U3.30(RXD_0/PHYAD1) U5.L4(RX_D{1}[0])
PR2_MII1_RXD1: R17.1 U3.31(RXD_1/PHYAD2) U5.M5(RX_D{1}[1]/EBUS{1}-RX+)
PR2_MII1_RXD2: R16.1 U3.32(RXD_2/PHYAD3) U5.L5(RX_D{1}[2])
PR2_MII1_RXD3: R15.1 U3.1(RXD_3/PHYAD4) U5.M6(RX_D{1}[3])
PR2_MII1_RXDV: R37.1 R38.2 TP8.1 U3.26(RX_DV/MII_MODE) U5.M4(RX_DV{1}/EBUS{1}-RX-)
PR2_MII1_RXER: R31.1 R32.2 U3.28(RX_ER/AMDIX_EN) U5.L6(RX_ERR{1})
PR2_MII1_RXLINK: P1.10(C_RIGHT) R41.2 TP9.1 U3.17(LED_LINK/AN_0) U5.K3(LINK_MII{1})
PR2_MII1_TXD0: R28.1 U3.4(TXD0) U5.L3(TX_D{1}[0]/TRANS-MODE-ENA)
PR2_MII1_TXD1: U3.5(TXD1) U5.M2(TX_D{1}[1]/EBUS{1}-TX-)
PR2_MII1_TXD2: R27.1 U3.6(TXD2) U5.L2(TX_D{1}[2]/P-MODE[0])
PR2_MII1_TXD3: R26.1 U3.7(TXD3) U5.M1(TX_D{1}[3]/P-MODE[1])
PR2_MII1_TXEN: TP1.1 U3.3(TX_EN) U5.M3(TX_ENA{1}/EBUS{1}-TX+)
PR2_MII_RESETN: U1.4(O) U3.18(RESETN) U5.H12(RESETN) U6.18(RESETN)
PR2_MII_XI: TP13.1 U3.23(XI) U5.F2(LINK_MII{2}/CLK25OUT) U6.23(XI)
REG_5V_IN: J10.2 L1.1
N21750864: R54.1 R55.2 U6.29(COL/PHYAD0)
N21750872: R61.1 R62.2 U6.27(CRS/CRS_DV/LED_CFG)
N21750878: R65.1 U6.16(RBIAS)
N21751363: P0.9(A_RIGHT) R74.1
N21751679: C83.2 P0.4(CHS_GND4) P0.5(CHS_GND3) P0.13(CHS_GND1) P0.14(CHS_GND2)
N21752228: R8.2 U6.8(INTN/PWDNN)
N21760792: R29.1 R30.2 U3.29(COL/PHYAD0)
N21760889: R35.1 R36.2 U3.27(CRS/CRS_DV/LED_CFG)
N21760945: P1.9(A_RIGHT) R43.1
N21760963: C41.2 P1.4(CHS_GND4) P1.5(CHS_GND3) P1.13(CHS_GND1) P1.14(CHS_GND2)
N21761103: R40.1 U3.16(RBIAS)
N21761294: R1.2 U3.8(INTN/PWDNN)
N21764803: C7.1 U5.F12(OSC_OUT) Y1.1(Y1)
N21764807: C3.1 U5.G12(OSC_IN) Y1.3(Y2)
N21767563: R19.1 U5.C4(RBIAS)
N21781367: TP7.1 U3.2(TX_CLK)
N21781382: TP11.1 U6.2(TX_CLK)
N21785424: DS1.1(CATHODE) R72.2
N21788279: P1.12(A_LEFT) R14.1
N21789027: P0.12(A_LEFT) R51.1
N21791162: R21.2 TP4.1 U5.F1(TX_ENA{2]/EBUS{2}-TX+)
N21791165: TP5.1 U5.E1(TX_D{2}[1]/EBUS{2}-TX-)
N21791168: TP2.1 U5.J1(RX_D{2}[1]/EBUS{2}-RX+)
N21791171: TP3.1 U5.H1(RX_DV{2}/EBUS{2}-RX-)
N21791186: TP6.1 U5.C1(PDI[31]/CLK25OUT2)
N21791230: R39.2 U5.A4(PDI[22]/TX_D{3}[3]) U5.C10(PDI[05])
N21823994: C4.1 C5.1 J3.3 L2.2 U8.4(FB)
N21823999: L2.1 U8.2(SW)
N21824161: C6.1 C8.1 C9.1 L1.2 U8.5(EN) U8.7(AVIN) U8.8(PVIN)
N21833989: J6.54 R7.1
N21833992: J6.55 R6.2
N21843407: R33.1 SW1.4(A4) U7.1(S)
N21843411: R34.1 SW1.3(A3) U2.19(O\E\)
N21843710: R58.2 U7.15(O\E\)
N21870681: J9.1 J10.3
N21871502: DS2.1(CATHODE) R75.2

Pads without a net: J6 2 46 58 59; R70 1 2; R71 1 2; U1 1; U2 1; U3 22; U6 22

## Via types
v1: diameter 0.508, hole 0.254, TOP to BOTTOM, 306 vias
v2: diameter 0.457, hole 0.203, TOP to BOTTOM, 106 vias
v3: diameter 0.61, hole 0.305, TOP to BOTTOM, 2 vias

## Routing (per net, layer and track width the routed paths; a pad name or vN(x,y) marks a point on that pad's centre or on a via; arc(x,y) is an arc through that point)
GND: length 143
  TOP w0.305: C7.2 v1(50.29,10.41) 50.29,10.79 50.6,11.1 Y1.4 ; C8.2 v1(56.9,10.79) ; v1(54.74,13.08) 55.37,13.08 C6.2 55.37,12.32 v1(54.74,12.32) ; SW1.2 SW1.1 v1(61.72,33.02) ; C9.2 v1(56.9,9.65) ; U8.1 62.43,8.59 v1(62.23,8.38) ; U5.G4 v2(51.27,27.8) ; RJ1.3 v1(57.91,19.18) ; Y1.2 52.53,15.06 52.83,15.37 v1(52.83,15.75) C3.2 ; C5.2 v1(60.71,11.81) ; U5.E4 v2(53.67,27.8) ; U5.E10 v2(53.67,22.2) ; U5.D5 v2(54.47,27) ; U5.D7 v2(54.47,24.6) ; U5.H3 v2(50.47,28.6) ; U5.J6 v2(49.67,26.2) ; v1(61.09,13.08) 61.72,13.08 C4.2 61.72,13.84 v1(61.09,13.84) ; U5.H10 v2(50.47,22.2) ; U5.J5 v2(49.67,27) ; U5.D9 v2(54.47,23) ; U5.D4 v2(54.47,27.8) ; U2.10 v1(71.56,28.26) ; U7.8 v1(71.75,20.06) ; U5.D8 v2(54.47,23.8) ; U5.J9 v2(49.67,23) ; U5.K9 v2(48.87,23) ; U8.3 v1(63.11,10.03) ; U5.F4 v2(52.87,27.8) ; RJ2.3 v1(57.15,17.14) ; U5.F9 v2(52.87,23) ; U5.G3 v2(51.27,28.6) ; U5.J8 v2(49.67,23.8) ; U8.6 v1(59.82,10.03) ; U5.C8 v2(55.27,23.8) ; U5.G9 v2(51.27,23) ; U5.J4 v2(49.67,27.8) ; U5.D6 v2(54.47,26.2) ; U5.H4 v2(50.47,27.8) ; U5.J7 v2(49.67,24.6)
  TOP w0.508: U4.1 v1(51.31,39.37) ; U4.2 v1(51.31,38.1) ; U1.3 v1(44.42,10.52) ; U4.4 v1(51.31,35.56) ; C1.2 28.07,32 v1(27.56,32) ; U4.7 v1(54.1,38.1) ; U4.3 v1(51.31,36.83) ; C2.2 27.94,17.27 v1(27.43,16.76) ; TP15.1 v1(30.86,9.27)
  L2_GND w0.305: J9.2 75.38,8.26 ; J9.2 73.47,8.26 ; J9.2 74.42,9.21 ; J9.2 74.42,7.3
  BOTTOM w0.254: J6.19 67.6,36.41 v1(67.69,36.32) ; J6.29 65.61,36.4 v1(65.53,36.32) ; J6.1 71.2,36.37 v1(71.25,36.32) ; J6.42 v1(63.21,41.11) ; J6.51 61.21,36.58 61.33,36.46 v1(61.33,36.13) ; J6.10 v1(69.6,41.14)
  BOTTOM w0.305: v1(40.39,32.38) 40.6,32.6 R37.2 R35.2 R31.2 R29.2 R22.2 R17.2 R16.2 R15.2 ; R48.2 R49.2 R50.2 R52.2 R54.2 R56.2 R61.2 R63.2 v1(41.27,17.27) ; R75.1 v1(39.5,10.29) R72.1
  BOTTOM w0.508: C79.2 v1(22.86,15.37) ; C22.2 v1(46.6,33.78) ; C77.2 v1(13.08,17.14) ; R58.1 v1(65.66,16.51) ; R46.2 v1(40.64,25.27) ; R24.2 v1(51.31,35.56) ; v1(23.11,12.32) C82.2 ; C67.2 v1(49.53,17.14) ; C17.2 v1(27.81,33.91) ; C36.2 v1(43.81,29.84) ; C81.2 v1(33.15,12.83) ; v1(20.83,8.26) 20.32,8.26 C83.1 20.32,7.24 v1(20.83,7.24) ; 45.72,36.45 v1(45.72,37.21) ; C13.2 v1(14.22,38.23) ; R20.2 v1(55.88,33.66) ; C45.2 v1(60.33,26.04) ; C49.2 v1(43.81,24.77) ; C11.1 27.05,39.88 v1(26.92,40.01) ; R45.2 v1(40.64,26.42) ; R40.2 v1(29.97,27.94) ; v1(20.83,27.05) 20.32,27.05 C41.1 20.32,28.07 v1(20.83,28.07) ; C63.2 v1(54.61,17.14) ; C52.2 v1(43.81,23.5) ; C55.2 v1(28.7,23.25) ; R67.2 v1(47.5,12.06) ; C54.2 v1(43.81,22.23) ; R18.2 v1(57.15,33.66) ; 44.58,36.45 v1(44.58,37.21) ; C74.2 C78.2 v1(26.67,14.85) ; C14.2 v1(13.08,36.2) ; C28.2 v1(53.34,33.66) ; C26.2 C34.2 v1(26.8,29.97) ; C19.2 v1(66.04,22.86) ; C48.2 v1(60.33,24.77) ; C15.1 v1(28.7,34.8) ; R73.2 v1(41.27,10.16) ; C20.2 v1(22.86,34.42) ; C10.2 v1(47.24,9.4) ; C42.2 v1(60.33,27.3) ; R21.1 v1(51.31,39.37) ; R39.1 v1(62.74,30.1) ; v1(23.11,31.37) C33.2 ; C35.2 v1(60.33,29.84) ; C56.2 v1(60.33,20.95) ; C53.2 v1(60.33,22.23) ; C50.2 v1(27.94,23.75) ; C40.2 v1(43.81,28.57) ; 43.43,36.45 v1(43.43,37.21) ; C27.2 v1(54.61,33.66) ; C69.2 v1(14.22,19.18) ; C31.2 v1(49.53,33.66) ; C46.2 v1(43.81,26.04) ; C66.2 v1(50.8,17.14) ; C39.2 v1(60.33,28.57) ; C64.2 v1(53.34,17.14) ; C65.2 v1(52.07,17.14) ; 35.05,13.34 v1(34.02,13.34) ; C47.1 v1(53.98,39.37) ; R59.2 v1(46.99,17.14) ; R19.2 v1(58.42,33.66) ; C51.2 v1(60.33,23.5) ; C44.2 v1(61.47,27.83) ; C37.2 v1(33.15,28.32) ; C29.2 v1(52.07,33.66) ; C12.2 v1(29.72,37.47) ; C60.1 v1(27.69,18.67) ; R65.2 v1(29.97,12.7) ; C68.2 v1(48.26,17.14) ; C75.2 v1(65.66,15.37) ; C38.2 v1(34.15,28.7) ; C58.1 v1(28.7,19.56) ; C62.2 v1(55.88,17.14) ; C57.2 v1(43.81,20.95) ; C43.2 v1(43.81,27.3) ; R47.2 v1(40.64,24.13) ; C30.2 v1(50.8,33.66)
  vias: v1(32.38,35.69) v1(32.38,34.29) v1(32.38,20.45) v1(32.38,19.05) v1(33.15,34.92) v1(33.15,19.68) v1(33.91,35.69) v1(33.91,34.29) v1(34.04,20.45) v1(34.04,19.05) v3(61.47,10.21) v3(61.47,9.35)
VCC_2V5: length 11.4
  TOP w0.305: U5.C7 v2(55.27,24.6) ; U5.K7 v2(48.87,24.6) ; U5.K6 v2(48.87,26.2) ; U5.C6 v2(55.27,26.2) ; U5.G10 v2(51.27,22.2)
  BOTTOM w0.508: C52.1 v1(46.35,23.5) ; C65.1 v1(52.07,19.68) ; C51.1 v1(57.78,23.5) ; C46.1 v1(46.35,26.04) ; C44.1 v1(61.47,24.5) ; C45.1 v1(57.78,26.04) ; C49.1 v1(46.35,24.77) ; C48.1 v1(57.78,24.77) ; C43.1 v1(46.35,27.3) ; C66.1 v1(50.8,19.68) ; C42.1 v1(57.78,27.3)
VCC_3V3: length 8.2
  TOP w0.305: J3.1 74.04,13.93 ; J3.1 74.04,11.98 ; J3.1 75.02,12.95 ; J3.1 73.06,12.95
  BOTTOM w0.254: v1(60.71,35.69) 60.71,36.2 60.81,36.3 J6.53 ; J6.57 60.01,36.51 v1(59.82,36.32) ; J6.52 61.21,40.89 v1(61.47,41.15) ; J6.56 60.41,41.07 v1(60.33,41.15)
CLK_MODE[0]: length 9
  TOP w0.127: U5.J11 49.67,21.4 49.67,20.46 49.02,19.81 49.02,16.76 47.5,15.24 v1(47.5,14.61)
  BOTTOM w0.127: v1(47.5,14.61) R67.1
CLK_MODE[1]: length 6.5
  TOP w0.305: U5.K2 v2(48.87,29.4)
  BOTTOM w0.127: v2(48.87,29.4) 48.28,29.99 48.28,30.5 48.77,30.99 48.77,33.78 R24.1
EEPROM_SIZE: length 17.9
  TOP w0.127: v1(43.05,11.43) DS1.2
  TOP w0.305: U5.H11 v2(50.47,21.4)
  BOTTOM w0.127: v2(50.47,21.4) 48.07,21.4 46.74,20.07 45.09,20.07 43.05,18.03 v1(43.05,11.43) R73.1
EM2A9: length 27
  TOP w0.127: U2.2 70.93,23.18 v1(71.5,23.75)
  BOTTOM w0.127: v1(71.5,23.75) 72.52,24.77 73.03,24.77 73.53,25.27 73.53,26.8 74.42,27.69 74.42,39.88 72.14,42.16 69.85,42.16 69.16,41.47 69.16,40.96 69.2,40.91 J6.12
EM2A10: length 16.6
  TOP w0.127: U2.3 v1(67.69,23.81)
  BOTTOM w0.127: v1(67.69,23.81) 67.18,24.32 67.18,25.53 67.82,26.16 67.82,33.53 68.8,34.51 J6.13
EM2A11: length 27.7
  TOP w0.127: U2.4 71.44,24.45 73.03,26.04 v1(73.98,26.04)
  BOTTOM w0.127: v1(73.98,26.04) 74.74,26.79 74.74,40.2 72.39,42.55 69.72,42.55 68.89,41.71 68.89,40.95 68.8,40.86 J6.14
EM2D1: length 18.1
  TOP w0.127: v1(67.69,24.89) 68.14,24.89 68.33,25.08 U2.5
  L4_ROUTE w0.127: v1(67.2,38.73) 67.2,34.02 67.75,33.46 67.75,25.4 67.69,25.34 v1(67.69,24.89)
  BOTTOM w0.127: J6.22 v1(67.2,38.73)
EM2D2: length 14.3
  TOP w0.127: v1(66.93,26.54) 68.07,26.54 68.26,26.35 U2.7
  BOTTOM w0.127: v1(66.93,26.54) 66.93,28.19 66.29,28.83 66.29,29.34 66.8,29.85 J6.23
EM2D3: length 23.2
  TOP w0.127: v1(66.04,25.4) 68.07,25.4 68.39,25.72 U2.6
  L4_ROUTE w0.127: v1(66.99,41.91) 66.99,40.45 66.67,40.13 66.67,33.78 67.25,33.21 67.25,27.88 66.03,26.66 66.03,25.85 66.04,25.84 v1(66.04,25.4)
  BOTTOM w0.127: v1(66.99,41.91) 66.99,40.96 66.8,40.78 J6.24
EM2D4: length 13.6
  TOP w0.127: U2.8 68.64,26.99 67.69,27.94 v1(66.42,27.94)
  BOTTOM w0.127: J6.25 66.41,30.08 65.98,29.66 65.98,28.38 v1(66.42,27.94)
EM2D11: length 14.1
  TOP w0.127: U2.9 68.9,27.62 66.55,29.97 v1(64.52,29.97)
  BOTTOM w0.127: J6.37 64.01,36.8 63.94,36.74 63.94,35.75 64.26,35.43 64.26,34.42 64.64,34.04 64.64,30.54 64.52,30.42 v1(64.52,29.97)
ET_ADDR1: length 27.9
  TOP w0.305: U5.B5 v2(56.07,27)
  L3_ROUTE w0.127: v2(56.07,27) 56.48,27.41 57.12,27.41 57.53,27.81 60.49,27.81 61.38,26.92 64.52,26.92 65.02,27.43 68.45,27.43 70.23,29.21 v1(72.77,29.21)
  BOTTOM w0.127: J6.3 70.8,36.51 70.79,36.5 70.79,36.01 72.96,33.85 72.96,30.41 72.77,30.23 v1(72.77,29.21)
ET_ADDR2: length 32.5
  TOP w0.305: U5.A5 v2(56.87,27)
  L3_ROUTE w0.127: v2(56.87,27) 57.46,27 57.6,26.86 57.97,26.86 58.11,27 60,27 60.14,26.86 60.77,26.86 60.96,26.67 64.62,26.67 64.95,27 68.78,27 69.6,27.81 72.39,27.81 v1(72.77,28.19)
  BOTTOM w0.127: J6.4 70.8,40.83 70.99,41.02 71.63,41.02 73.28,39.37 73.28,28.7 v1(72.77,28.19)
ET_ADDR3: length 28.2
  TOP w0.305: U5.B6 v2(56.07,26.2)
  L3_ROUTE w0.127: v1(71.63,27.18) 69.98,27.18 68.83,26.04 66.68,26.04 66.42,26.29 60.83,26.29 60.64,26.48 57.91,26.48 57.78,26.61 56.48,26.61 v2(56.07,26.2)
  BOTTOM w0.127: J6.5 70.4,35.9 72.52,33.78 72.52,30.73 72.14,30.35 72.14,27.69 v1(71.63,27.18)
ET_ADDR4: length 35
  TOP w0.305: U5.A6 v2(56.87,26.2)
  L3_ROUTE w0.127: v1(71.63,26.29) 69.98,26.29 69.34,25.65 66.55,25.65 66.36,25.84 61.15,25.84 60.9,25.59 57.6,25.59 57.54,25.65 57.42,25.65 v2(56.87,26.2)
  BOTTOM w0.127: J6.6 70.4,40.94 70.87,41.4 71.75,41.4 73.66,39.5 73.66,28.32 v1(71.63,26.29)
ET_ADDR5: length 30.3
  TOP w0.305: U5.B7 v2(56.07,24.6)
  L3_ROUTE w0.127: v2(56.07,24.6) 56.87,25.4 57.31,25.4 57.44,25.27 65.28,25.27 65.66,24.89 66.67,24.89 67.12,25.34 v1(71.63,25.34)
  BOTTOM w0.127: v1(71.63,25.34) 71.12,25.84 71.12,30.23 72.2,31.31 72.2,33.59 70,35.79 J6.7
ET_ADDR6: length 38.4
  TOP w0.305: U5.A7 v2(56.87,24.6)
  L3_ROUTE w0.127: v2(56.87,24.6) 57.32,24.6 57.54,24.38 57.6,24.32 60.64,24.32 61.34,25.02 64.64,25.02 65.28,24.38 72.01,24.38 v1(73.03,25.4)
  BOTTOM w0.127: J6.8 70,40.91 70.87,41.78 71.88,41.78 74.04,39.62 74.04,27.94 73.03,26.92 v1(73.03,25.4)
ET_ADDR7: length 28.2
  TOP w0.305: U5.B8 v2(56.07,23.8)
  L3_ROUTE w0.127: v2(56.07,23.8) 56.46,24.19 57.24,24.19 57.49,23.94 65.98,23.94 66.8,23.11 v1(68.58,23.11)
  BOTTOM w0.127: v1(68.58,23.11) 68.58,33.27 69.6,34.3 J6.9
ET_ADDR8: length 27.5
  TOP w0.305: U5.A8 v2(56.87,23.8)
  L3_ROUTE w0.127: v1(67.82,22.61) 67.44,22.23 62.48,22.23 61.66,23.05 57.6,23.05 57.15,23.5 57.15,23.52 v2(56.87,23.8)
  BOTTOM w0.127: J6.11 69.2,34.4 68.2,33.4 68.2,23.5 67.82,23.11 v1(67.82,22.61)
ET_ADDR9: length 9.6
  TOP w0.127: U2.18 63.31,23.81 62.23,22.73 57.15,22.73 56.88,23 56.07,23 U5.B9
ET_ADDR10: length 8.8
  TOP w0.127: U2.17 63.44,24.45 62.04,23.05 57.34,23.05 56.99,23.4 U5.A9
ET_ADDR11: length 10.9
  TOP w0.127: v1(61.47,23.5) 63.06,25.08 U2.16
  TOP w0.305: U5.C9 v2(55.27,23)
  BOTTOM w0.127: v1(61.47,23.5) 60.83,22.86 57.28,22.86 57.14,23 v2(55.27,23)
ET_ADDR12: length 28.3
  TOP w0.127: U5.A10 56.78,22.6 57.69,21.69 67.98,21.69 v1(68.29,22)
  L4_ROUTE w0.127: v1(68.33,34.8) 68.33,30.73 69.22,29.84 69.22,22.92 v1(68.29,22)
  BOTTOM w0.127: J6.15 68.4,35.38 68.33,35.31 v1(68.33,34.8)
ET_ADDR13: length 36.3
  TOP w0.127: U5.B10 56.07,22.2 56.79,22.2 57.56,21.43 68.42,21.43 68.64,21.21 v1(69.09,21.21)
  L4_ROUTE w0.127: v1(68.39,41.3) 68.39,40.85 68.4,40.84 68.4,39.12 70.23,37.29 70.23,22.8 69.09,21.65 v1(69.09,21.21)
  BOTTOM w0.127: J6.16 68.4,40.84 68.39,40.85 v1(68.39,41.3)
ET_ADDR14: length 4.4
  TOP w0.127: RJ1.2 58.93,18.92 57.34,20.51 57.34,20.93 U5.A11
ET_ADDR15: length 6.5
  TOP w0.127: RJ2.2 58.29,17.78 57.53,17.78 57.28,18.03 57.28,19.56 56.07,20.76 56.07,21.4 U5.B11
ET_BUSY: length 24.4
  TOP w0.127: U7.11 v1(62.87,18.76)
  L4_ROUTE w0.127: v1(61.59,38.73) 62.61,37.72 62.61,31.11 63.37,30.35 63.37,28.7 63.88,28.19 63.88,19.77 v1(62.87,18.76)
  BOTTOM w0.127: J6.50 61.61,39.73 61.59,39.71 v1(61.59,38.73)
ET_BUSY/SPI_DO: length 15.5
  TOP w0.127: U7.9 63.11,20.06 61.34,18.29 61.34,17.4 60.45,16.51 57.02,16.51 56.52,17.02 56.52,17.78 55.44,18.86 55.44,20.26 55.27,20.42 55.27,21.4 U5.C11
ET_CS: length 23.6
  TOP w0.127: U7.5 v1(68.33,18.11)
  BOTTOM w0.127: v1(68.33,18.11) 66.29,20.14 66.29,21.46 66.55,21.72 66.55,23.37 65.41,24.51 65.41,27.3 64.07,28.64 64.07,30.8 63.63,31.24 63.63,33.15 62.74,34.04 62.74,36.59 62.81,36.65 J6.43
ET_CS/SPI_CLK: length 24.6
  TOP w0.127: U5.D12 54.07,16.67 55.12,15.62 61.59,15.62 62.29,14.92 66.23,14.92 67.31,16 67.31,18.54 68.17,19.41 U7.7
ET_DATA0: length 20.8
  TOP w0.305: U5.B4 v2(56.07,27.8)
  L3_ROUTE w0.127: v1(66.8,29.02) 65.6,29.02 63.94,27.37 61.3,27.37 60.53,28.13 57.1,28.13 57.03,28.19 56.46,28.19 v2(56.07,27.8)
  BOTTOM w0.127: J6.21 67.2,29.42 v1(66.8,29.02)
ET_DATA1: length 9.2
  TOP w0.127: U2.15 62.29,25.72 61.34,26.67 59.82,26.67 58.67,27.81 57.66,27.81 57.28,28.19 56.83,28.19 56.82,28.2 U5.A3
ET_DATA2: length 10.6
  TOP w0.127: U2.13 63.44,26.99 62.99,27.43 62.99,28.07 61.85,29.21 57.66,29.21 57.05,28.6 56.07,28.6 U5.B3
ET_DATA3: length 10
  TOP w0.127: U2.14 63.25,26.35 62.42,27.18 62.42,27.88 v1(62.1,28.19)
  TOP w0.305: U5.A2 v2(56.87,29.4)
  L3_ROUTE w0.127: v1(62.1,28.19) 61.17,29.13 57.14,29.13 v2(56.87,29.4)
ET_DATA4: length 9.9
  TOP w0.127: U2.12 63.51,27.62 63.37,27.76 63.37,28.32 61.72,29.97 61.21,29.97 60.71,30.48 57.15,30.48 U5.A1
ET_DATA5: length 22.8
  TOP w0.127: U5.B2 56.07,29.4 56.07,29.91 57.53,31.37 61.59,31.37 62.1,30.86 65.2,30.86 v1(65.96,31.62)
  L4_ROUTE w0.127: v1(65.96,31.62) 66.28,31.94 66.28,40.43 66.55,40.7 v1(66.55,41.15)
  BOTTOM w0.127: v1(66.55,41.15) 66.41,41.01 J6.26
ET_DATA6: length 14.9
  TOP w0.127: U5.B1 55.67,30.15 58.16,32.64 60.33,32.64 61.47,33.78 64.9,33.78 v1(65.79,34.67)
  BOTTOM w0.127: v1(65.79,34.67) 65.79,35.69 66,35.91 J6.27
ET_DATA7: length 22.6
  TOP w0.127: v1(58.04,39.75) 58.04,35.31 56.39,33.66 56.39,31.5 55.27,30.38 55.27,29.4 U5.C2
  L3_ROUTE w0.127: v1(66.17,41.78) 64.14,39.75 v1(58.04,39.75)
  BOTTOM w0.127: v1(66.17,41.78) 66,41.62 J6.28
ET_DATA8: length 22.6
  TOP w0.127: v1(56.64,41.02) 57.98,42.35 63.96,42.35 v1(64.33,41.98)
  TOP w0.305: U5.D1 v2(54.47,30.2)
  L4_ROUTE w0.127: v1(56.64,41.02) 56.64,35.31 55.24,33.91 55.24,30.98 v2(54.47,30.2)
  BOTTOM w0.127: J6.34 64.81,40.9 64.85,40.95 64.85,41.47 v1(64.33,41.98)
ET_DATA9: length 20.4
  TOP w0.305: U5.D2 v2(54.47,29.4)
  L3_ROUTE w0.127: v2(54.47,29.4) 55.42,30.35 60.96,30.35 62.23,29.08 v1(64.83,29.08)
  BOTTOM w0.127: J6.35 64.41,36.72 64.2,36.51 64.2,36.01 64.64,35.56 64.64,34.54 65.02,34.16 65.02,29.72 64.83,29.53 v1(64.83,29.08)
ET_DATA10: length 25
  TOP w0.305: U5.E2 v2(53.67,29.4)
  L3_ROUTE w0.127: v1(64.41,41.13) 63.88,41.66 63.88,42.29 63.25,42.93 56.64,42.93 v1(55.63,41.91)
  L4_ROUTE w0.127: v1(55.63,41.91) 54.86,41.15 54.86,34.92 53.91,33.97 53.91,30.67 53.67,30.43 v2(53.67,29.4)
  BOTTOM w0.127: J6.36 v1(64.41,41.13)
ET_DATA11: length 15.2
  TOP w0.127: U2.11 63.88,28.26 63.62,28.52 63.62,28.52 v1(61.34,30.8)
  TOP w0.305: U5.G1 v2(51.27,30.2)
  L3_ROUTE w0.127: v1(61.34,30.8) 55.18,30.8 55.05,30.67 53.91,30.67 53.44,30.2 v2(51.27,30.2)
ET_DATA12: length 26.8
  TOP w0.305: U5.G2 v2(51.27,29.4)
  BOTTOM w0.127: J6.38 64.01,40.9 63.9,41 63.9,41.61 63.75,41.76 63.75,42.29 63.25,42.8 54.99,42.8 53.09,40.89 53.09,35.94 51.44,34.29 51.44,30.73 51.66,30.51 51.66,29.79 v2(51.27,29.4)
ET_DATA13: length 21.9
  TOP w0.305: U5.H2 v2(50.47,29.4)
  L3_ROUTE w0.127: v2(50.47,29.4) 50.47,30.02 51.31,30.86 51.31,31.37 51.69,31.75 61.98,31.75 62.23,31.5 v1(64.14,31.5)
  BOTTOM w0.127: J6.39 63.61,35.58 63.88,35.31 63.88,34.16 64.14,33.91 v1(64.14,31.5)
ET_DATA14: length 28.3
  TOP w0.305: U5.J2 v2(49.67,29.4)
  L3_ROUTE w0.127: v1(63.25,41.91) 62.61,42.55 57.28,42.55 56.01,41.27 v1(50.16,41.27)
  L4_ROUTE w0.127: v2(49.67,29.4) 49.67,30.24 50.16,30.73 v1(50.16,41.27)
  BOTTOM w0.127: v1(63.25,41.91) 63.65,41.51 63.65,40.92 63.61,40.88 J6.40
ET_DATA15: length 20.1
  TOP w0.305: U5.K1 v2(48.87,30.2)
  L3_ROUTE w0.127: v1(63.25,34.42) 61.72,34.42 59.56,32.26 49.78,32.26 48.87,31.34 v2(48.87,30.2)
  BOTTOM w0.127: v1(63.25,34.42) 63.25,34.86 63.21,34.9 J6.41
ET_EE_LOADED: length 61.9
  TOP w0.127: v1(67.6,42.67) 67.1,43.18 64.77,43.18 64.39,42.8 45.34,42.8 TP16.1
  TOP w0.305: U5.A12 v2(56.87,20.6)
  L3_ROUTE w0.127: v1(68.2,20.7) 67.75,20.26 57.21,20.26 v2(56.87,20.6)
  L4_ROUTE w0.127: v1(68.2,20.7) 68.2,21.21 69.85,22.86 69.85,36.83 68.07,38.61 68.07,40.51 67.6,40.98 v1(67.6,42.67)
  BOTTOM w0.127: J6.20 v1(67.6,42.67)
ET_IRQ/SPI_IRQ: length 24.7
  TOP w0.127: U5.B12 55.67,20.65 56.39,19.93 56.39,19.68 v1(56.77,19.3)
  L4_ROUTE w0.127: v1(56.77,19.3) 57.21,19.3 59.5,21.59 60.71,21.59 62.74,23.62 62.74,28.32 60.9,30.16 60.9,33.59 61.59,34.29 v1(61.59,35.43)
  BOTTOM w0.127: J6.49 61.61,36.65 61.78,36.48 61.78,35.62 v1(61.59,35.43)
ET_RD: length 33
  TOP w0.127: v1(67.94,16.64) 68.43,16.15 U7.2
  L4_ROUTE w0.127: v1(67.94,16.64) 66.42,16.64 64.39,18.67 64.39,28.45 63.88,28.96 63.88,30.61 63.63,30.86 63.63,31.88 63.82,32.07 63.82,38.93 62.36,40.39 v1(62.36,41.91)
  BOTTOM w0.127: J6.44 62.81,40.88 62.67,41.01 62.67,41.6 v1(62.36,41.91)
ET_RD/SPI_SEL: length 18.8
  TOP w0.127: v1(67.94,17.4) 69.16,17.4 69.22,17.45 U7.4
  TOP w0.305: U5.D11 v2(54.47,21.4)
  L3_ROUTE w0.127: v2(54.47,21.4) 54.47,20.84 55.12,20.19 55.12,19.43 56.51,18.03 66.68,18.03 67.31,17.4 v1(67.94,17.4)
ET_RESETN: length 47.2
  TOP w0.127: U1.2 45.85,11.18 v1(45.34,11.68)
  L4_ROUTE w0.127: v1(59.44,41.15) 57.91,41.15 56.52,42.55 49.91,42.55 45.21,37.85 45.21,33.4 44.45,32.64 44.45,16.51 45.34,15.62 v1(45.34,11.68)
  BOTTOM w0.127: v1(45.34,11.68) 45.21,11.56 R13.1 ; 59.61,40.09 J6.60 59.61,40.98 v1(59.44,41.15)
ET_SCL: length 24.4
  TOP w0.127: v1(57.53,36.83) U4.6 v1(53.85,36.83)
  TOP w0.305: U5.G11 v2(51.27,21.4)
  L4_ROUTE w0.127: v2(51.27,21.4) 51.82,21.95 51.82,30.35 51.44,30.73 51.44,34.42 v1(53.85,36.83)
  BOTTOM w0.127: R7.2 57.15,37.85 57.53,37.47 v1(57.53,36.83) R44.1
ET_SDA: length 21.8
  TOP w0.127: v1(53.47,35.56) U4.5 v1(57.53,35.56)
  TOP w0.305: U5.F11 v2(52.87,21.4)
  L4_ROUTE w0.127: v1(53.47,35.56) 52.58,34.67 52.58,30.73 52.2,30.35 52.2,22.07 v2(52.87,21.4)
  BOTTOM w0.127: R6.1 v1(57.53,35.56) R42.1
ET_SPI_CLK: length 22
  TOP w0.127: U7.6 v1(68.83,18.76)
  BOTTOM w0.127: v1(68.83,18.76) 68.37,18.76 66.67,20.45 66.67,21.21 66.93,21.46 66.93,23.62 66.48,24.07 66.48,26.86 65.47,27.88 65.47,34.23 65.09,34.61 65.09,36.51 65.2,36.62 J6.31
ET_SPI_DI: length 30.4
  TOP w0.127: U7.13 v1(66.42,17.45)
  L4_ROUTE w0.127: v1(65.15,42.55) 65.15,42.1 65.28,41.97 65.28,37.22 65.09,37.02 65.09,31.31 65.66,30.73 65.66,27.3 65.53,27.18 65.53,24.77 66.55,23.75 66.55,21.34 66.42,21.21 v1(66.42,17.45)
  BOTTOM w0.127: v1(65.15,42.55) 65.15,41.82 65.2,41.77 J6.32
ET_SPI_DO: length 20
  TOP w0.127: v1(65.79,19.41) U7.10
  L4_ROUTE w0.127: v1(65.79,19.41) 65.79,21.84 65.02,22.61 65.02,27.94 65.28,28.19 65.28,30.23 64.64,30.86 v1(64.64,36.32)
  BOTTOM w0.127: J6.33 64.81,36.48 v1(64.64,36.32)
ET_SPI_SEL: length 42
  TOP w0.127: U7.3 v1(71.88,16.8)
  BOTTOM w0.127: J6.30 65.61,41.85 67.06,43.31 72.77,43.31 76.58,39.5 76.58,19.68 73.7,16.8 v1(71.88,16.8)
ET_SYNC0: length 25
  TOP w0.305: U5.E11 v2(53.67,21.4)
  BOTTOM w0.127: v2(53.67,21.4) 54.06,21.79 56.31,21.79 56.52,21.59 60.45,21.59 63.37,24.51 63.37,30.35 62.61,31.11 62.61,32.89 62.04,33.46 62.04,36.58 62.01,36.62 J6.47
ET_SYNC1: length 31.8
  TOP w0.305: U5.E12 v2(53.67,20.6)
  L4_ROUTE w0.127: v2(53.67,20.6) 53.26,21.01 53.26,30.05 52.9,30.42 52.9,34.1 54.55,35.75 54.55,40.2 v1(54.23,40.51)
  BOTTOM w0.127: J6.48 62.01,41.63 61.21,42.42 56.9,42.42 55.63,41.15 54.86,41.15 v1(54.23,40.51)
ET_WR: length 23
  TOP w0.127: U7.14 63.2,16.8 v1(62.61,17.4)
  BOTTOM w0.127: J6.45 62.41,33.73 63.25,32.89 63.25,30.99 63.75,30.48 63.75,24.38 62.29,22.92 62.29,17.71 v1(62.61,17.4)
ET_WR/SPI_DI: length 14.6
  TOP w0.127: U5.C12 54.87,20.31 55.12,20.07 55.12,16.76 55.75,16.13 60.58,16.13 62.56,18.11 U7.12
EVM_3V3: length 121.7
  TOP w0.254: U3.14 29.21,34.17 v1(29.21,34.17) ; v1(29.21,18.93) 29.21,18.93 U6.14
  TOP w0.305: R8.1 v1(31.11,27.3) ; v1(29.21,18.93) 28.96,18.93 C2.1 ; DS2.2 42.9,9.65 v1(44.45,9.65) ; U2.20 63.44,22.54 v1(63.25,22.73) ; R12.2 v1(26.92,18.67) ; R10.2 v1(26.16,21.72) ; v1(27.05,33.91) 26.92,34.04 R5.2 ; U5.F3 v2(52.87,28.6) ; C1.1 29.21,34.16 v1(29.21,34.17) ; R1.1 v1(33.02,41.78) ; R2.2 v1(26.16,38.23) ; U5.J3 v2(49.67,28.6) ; v1(33.15,15.88) 33.4,16.13 U6.21 ; U5.D3 v2(54.47,28.6) ; R3.2 v1(26.16,36.96) ; U5.E9 v2(53.67,23) ; U5.K8 v2(48.87,23.8) ; U5.F10 v2(52.87,22.2) ; U3.21 33.4,31.37 v1(33.15,31.12) ; U5.K5 v2(48.87,27) ; U5.D10 v2(54.47,22.2) ; U7.16 63.13,15.5 v1(63.06,15.43) ; R4.2 v1(26.16,35.94) ; R9.2 v1(26.16,22.99) ; U5.H9 v2(50.47,23) ; U5.J10 v2(49.67,22.2) ; U5.C5 v2(55.27,27) ; R11.2 v1(26.16,20.7)
  TOP w0.508: U4.8 v1(55.79,40.22) ; U1.5 v1(47.24,8.53)
  L5_PWR w0.305: 72.04,12.05 J3.2 ; J3.2 72.94,12.95 ; J3.2 72.04,13.86 ; J3.2 71.14,12.95 ; 17.27,16.24 P0.6 ; P0.6 16.37,17.14 ; P0.6 17.27,18.05 ; P0.6 18.17,17.14 ; 17.27,35.29 P1.6 ; P1.6 18.17,36.2 ; P1.6 17.27,37.1 ; P1.6 16.37,36.2 ; P0.3 20.71,13.34 ; P0.3 19.81,12.43 ; P0.3 18.91,13.34 ; P0.3 19.81,14.24 ; P1.3 20.71,32.38 ; P1.3 19.81,31.48 ; P1.3 19.81,33.29 ; P1.3 18.91,32.38
  BOTTOM w0.305: R38.1 v1(37.88,32.55) ; v1(29.21,18.93) 29.85,18.93 C61.1 ; R64.1 v1(37.88,16.62) ; R43.2 v1(28.07,26.8) ; v1(29.21,34.17) 29.85,34.17 C18.1
  BOTTOM w0.381: R53.1 R55.1 R57.1 R62.1 R64.1 ; R23.1 R30.1 R32.1 R36.1 R38.1 ; v1(27.43,13.08) 27.39,13.04 R69.1 ; R41.1 v1(27.65,29.97)
  BOTTOM w0.508: C39.1 v1(57.78,28.57) ; C11.2 v1(26.16,38.23) ; C33.1 P1.3 ; C37.1 v1(33.15,31.12) ; v1(33.15,31.12) 33.78,31.75 C24.1 ; v1(33.15,31.12) 32.51,31.75 C25.1 ; C68.1 v1(48.26,19.68) ; C78.1 28.7,15.88 29.34,16.51 v1(29.34,17.14) C76.1 ; C31.1 v1(49.53,31.11) ; C81.1 v1(33.15,15.88) ; v1(33.15,15.88) 33.78,16.51 C72.1 ; v1(33.15,15.88) 32.51,16.51 C73.1 ; C38.1 v1(34.15,30.23) ; C67.1 v1(49.53,19.68) ; R60.2 v1(45.72,17.14) ; C13.1 v1(15.24,38.23) ; C27.1 v1(54.61,31.11) ; C35.1 v1(57.78,29.84) ; R34.2 v1(69.22,31.75) ; C19.1 63.37,22.86 v1(63.25,22.73) ; P0.6 C77.1 ; C50.1 v1(26.16,22.99) ; R33.2 v1(69.22,33.02) ; v1(26.16,21.72) 26.67,22.23 C55.1 ; C34.1 28.57,31.11 29.34,31.88 v1(29.34,32.38) C32.1 ; C10.1 47.09,8.38 v1(47.24,8.53) ; v1(26.92,18.67) 26.67,18.92 C60.2 ; C79.1 v1(21.84,15.37) ; C53.1 v1(57.78,22.23) ; C29.1 v1(52.07,31.11) ; R13.2 v1(44.45,9.65) ; C36.1 v1(46.35,29.84) ; C56.1 v1(57.78,20.95) ; v1(27.05,33.91) 26.8,34.16 C17.1 ; R74.2 v1(27.81,10.79) ; C54.1 v1(46.35,22.23) ; C12.1 26.67,37.47 v1(26.16,36.96) ; C63.1 v1(54.61,19.68) ; R68.2 v1(46.35,12.06) ; v1(63.06,15.43) 63.12,15.37 C75.1 ; C15.2 v1(26.16,35.94) ; C22.1 v1(47.62,31.36) ; C28.1 v1(53.34,31.11) ; C57.1 v1(46.35,20.95) ; C64.1 v1(53.34,19.68) ; 46.86,36.45 v1(46.86,37.21) ; C20.1 v1(21.84,34.42) ; R44.2 R42.2 v1(55.37,34.8) ; C80.1 v1(34.02,14.86) ; C30.1 v1(50.8,31.11) ; C82.1 P0.3 ; R51.2 v1(21.46,19.68) ; v1(21.46,40.77) R14.2 ; R66.2 v1(48.64,12.06) ; v1(55.79,40.22) 55.75,40.18 C47.2 ; C58.2 v1(26.16,20.7) ; C40.1 v1(46.35,28.57) ; P1.6 C14.1 ; C69.1 v1(15.24,19.18) ; C62.1 v1(55.88,19.68)
GPIO93: length 25.4
  TOP w0.127: RJ1.1 62.36,20.83 v1(67.18,20.83)
  BOTTOM w0.127: J6.17 68,36.64 68.14,36.51 68.14,35.75 67.56,35.18 67.56,26.42 66.8,25.65 66.8,24.26 67.18,23.88 v1(67.18,20.83)
GPIO94: length 49.2
  TOP w0.127: RJ2.1 60.45,17.14 60.83,17.53 60.83,18.29 63.12,20.57 65.91,20.57 66.42,20.07 v1(68.83,20.07)
  BOTTOM w0.127: J6.18 68,41.05 67.94,41.11 67.94,41.66 69.21,42.93 72.52,42.93 76.2,39.24 76.2,20.95 74.68,19.43 69.47,19.43 v1(68.83,20.07)
MII0_RXM1: length 15.8
  TOP w0.104: 17.27,19.68 17.91,19.05 18.35,19.05 20.86,21.56 23.15,21.56 24.07,22.49 27.44,22.49 R9.1 28.48,22.44 28.68,22.44 29.69,21.44 U6.9
MII0_RXP1: length 15.6
  TOP w0.104: U6.10 29.86,20.94 28.59,22.21 28.44,22.21 R10.1 27.4,22.26 24.16,22.26 23.24,21.34 20.95,21.34 18.8,19.18 18.8,18.8 19.18,18.41 P0.7
MII0_TXM1: length 19.2
  TOP w0.104: P0.2 17.65,11.68 18.63,11.68 19.24,12.29 21.56,12.29 25.93,16.66 25.93,19.65 26.48,20.2 27.44,20.2 R11.1 28.32,20.32 29.81,20.32 29.93,20.44 U6.11
